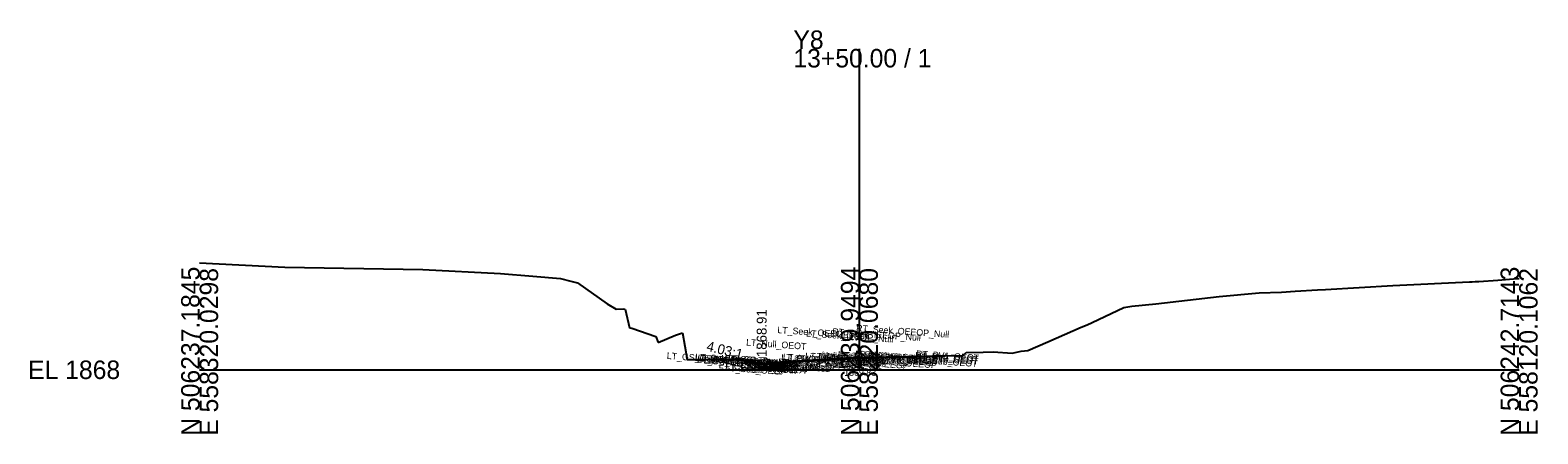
# Model space of a CAD drawing. Extents: x -26 to 203, y -10 to 8070.
# Drawn here: x -25.7 to 202.8, y 3490.3 to 3551.4 of the extents above; entities that cross this region are included whole.
import ezdxf

# ---------------------------------------------------------------- set-up
doc = ezdxf.new("R2010")
doc.units = 0
for name, color, linetype in [('Default', 7, 'Continuous'), ('Exist Cross Section Cell', 7, 'Continuous'), ('Exist XS Center Line Elevation Label', 7, 'Continuous'), ('Exist XS Ground Line', 7, 'Continuous'), ('Prop CMT Conc Surface', 7, 'Continuous'), ('Prop CMT Concrete Structures', 7, 'Continuous'), ('Prop CMT Pvmt Course 1', 7, 'Continuous'), ('Prop CMT Pvmt Course 1 CG', 7, 'Continuous'), ('Prop CMT Pvmt Course 2', 7, 'Continuous'), ('Prop CMT Pvmt Course 3', 7, 'Continuous'), ('Prop CMT Pvmt Surface', 7, 'Continuous'), ('Prop CMT Slope Grass', 7, 'Continuous'), ('Prop CMT Subgrade Earthwork', 7, 'Continuous'), ('Prop XS Earthwork Shape', 7, 'Continuous'), ('Prop XS Hydro Elevations', 7, 'Continuous'), ('Prop XS Side Slope Text', 7, 'Continuous'), ('Typical Text Grade Point CELL', 7, 'Continuous')]:
    doc.layers.add(name, color=color, linetype=linetype)

msp = doc.modelspace()

# ---------------------------------------------------------------- linework, layer by layer
at = {"layer": 'Exist Cross Section Cell'}
for p, q in [((100, 3500), (100, 3548.56)), ((0, 3500), (100, 3500)), ((100, 3500), (200, 3500))]:
    msp.add_line(p, q, dxfattribs=at)
at = {"layer": 'Exist XS Ground Line'}
for p, q in [((0, 3516.19), (12.91, 3515.51)), ((12.91, 3515.51), (33.83, 3515.19)), ((33.83, 3515.19), (45.59, 3514.57)), ((45.59, 3514.57), (50.52, 3514.17)), ((50.52, 3514.17), (54.72, 3513.79)), ((54.72, 3513.79), (56.24, 3513.4)), ((56.24, 3513.4), (57.29, 3513.14)), ((57.29, 3513.14), (61.75, 3510)), ((170.64, 3512.16), (180.87, 3512.74)), ((180.87, 3512.74), (192.5, 3513.31)), ((192.5, 3513.31), (192.88, 3513.33)), ((192.88, 3513.33), (193.33, 3513.34)), ((193.33, 3513.34), (193.91, 3513.35)), ((193.91, 3513.35), (196.79, 3513.55)), ((196.79, 3513.55), (199.13, 3513.74)), ((199.13, 3513.74), (200, 3513.8)), ((144.93, 3509.99), (154.51, 3511.07)), ((154.51, 3511.07), (160.62, 3511.63)), ((160.62, 3511.63), (163.97, 3511.76)), ((163.97, 3511.76), (166.08, 3511.88)), ((166.08, 3511.88), (169.43, 3512.09)), ((169.43, 3512.09), (170.64, 3512.16)), ((61.75, 3510), (63.11, 3509.15)), ((63.11, 3509.15), (64.18, 3509.2)), ((64.18, 3509.2), (64.5, 3509.19)), ((64.5, 3509.19), (65.15, 3506.35)), ((135.29, 3507.16), (140.06, 3509.41)), ((140.06, 3509.41), (141.29, 3509.61)), ((141.29, 3509.61), (144.93, 3509.99)), ((65.15, 3506.35), (65.51, 3506.32)), ((65.51, 3506.32), (69.16, 3505.02)), ((128.55, 3504.23), (133.62, 3506.43)), ((133.62, 3506.43), (134.53, 3506.82)), ((134.53, 3506.82), (135.29, 3507.16)), ((69.16, 3505.02), (69.49, 3504.12)), ((69.49, 3504.12), (72.11, 3505.22)), ((72.11, 3505.22), (73.2, 3505.61)), ((73.2, 3505.61), (73.89, 3501.56)), ((125.55, 3502.93), (128.55, 3504.23)), ((73.89, 3501.56), (74.57, 3501.54)), ((74.57, 3501.54), (75.66, 3501.54)), ((75.66, 3501.54), (78.42, 3501.56)), ((78.42, 3501.56), (80.12, 3501.53)), ((80.12, 3501.53), (83.51, 3501.43)), ((83.51, 3501.43), (84.06, 3500.96)), ((85.69, 3501.01), (88.95, 3501.21)), ((88.95, 3501.21), (99.03, 3501.81)), ((99.03, 3501.81), (100, 3501.83)), ((100, 3501.83), (100.64, 3501.84)), ((100.64, 3501.84), (113.89, 3502.17)), ((113.89, 3502.17), (114.62, 3502.17)), ((114.62, 3502.17), (115.63, 3502.11)), ((115.63, 3502.11), (116.21, 3502.61)), ((116.21, 3502.61), (118.75, 3502.68)), ((118.75, 3502.68), (120.28, 3502.73)), ((120.28, 3502.73), (123.18, 3502.51)), ((123.18, 3502.51), (124.52, 3502.8)), ((124.52, 3502.8), (125.55, 3502.93)), ((84.06, 3500.96), (84.5, 3500.97)), ((84.5, 3500.97), (85.69, 3501.01))]:
    msp.add_line(p, q, dxfattribs=at)
at = {"layer": 'Prop CMT Conc Surface'}
for points in [[(85.19, 3500.91), (85.19, 3501.41), (84.69, 3501.41)], [(87.19, 3501.1), (85.19, 3500.91)]]:
    msp.add_lwpolyline(points, dxfattribs=at)
at = {"layer": 'Prop CMT Concrete Structures'}
for points in [[(87.19, 3501.1), (85.19, 3500.91), (85.19, 3501.41), (84.69, 3501.41)], [(84.69, 3501.41), (84.69, 3500.38), (87.19, 3500.52)], [(87.19, 3500.52), (87.19, 3501.1)]]:
    msp.add_lwpolyline(points, dxfattribs=at)
at = {"layer": 'Prop CMT Pvmt Course 1'}
for points in [[(99.98, 3501.83), (97.98, 3501.75), (97.97, 3501.75), (93.99, 3501.51), (93.98, 3501.51), (87.19, 3501.1)], [(99.98, 3501.83), (101.98, 3501.88), (101.99, 3501.88), (105.97, 3501.98), (105.98, 3501.98), (112.77, 3502.14)], [(87.19, 3501.1), (87.19, 3500.85)], [(87.19, 3500.85), (88.69, 3500.94)]]:
    msp.add_lwpolyline(points, dxfattribs=at)
at = {"layer": 'Prop CMT Pvmt Course 1 CG'}
for points in [[(87.19, 3500.52), (84.19, 3500.35), (83.88, 3500.04)], [(83.88, 3500.04), (87.19, 3500.23)], [(87.19, 3500.23), (87.19, 3500.52)]]:
    msp.add_lwpolyline(points, dxfattribs=at)
at = {"layer": 'Prop CMT Pvmt Course 2'}
for points in [[(88.69, 3500.94), (87.19, 3500.85)], [(87.19, 3500.85), (87.19, 3500.6)], [(87.19, 3500.6), (88.69, 3500.69)]]:
    msp.add_lwpolyline(points, dxfattribs=at)
at = {"layer": 'Prop CMT Pvmt Course 3'}
for points in [[(88.69, 3500.69), (87.19, 3500.6)], [(87.19, 3500.6), (87.19, 3500.23)], [(87.19, 3500.23), (88.69, 3500.31)]]:
    msp.add_lwpolyline(points, dxfattribs=at)
at = {"layer": 'Prop CMT Pvmt Surface'}
for points in [[(99.98, 3501.83), (97.98, 3501.75), (97.97, 3501.75), (93.99, 3501.51), (93.98, 3501.51), (87.19, 3501.1)], [(99.98, 3501.83), (101.98, 3501.88), (101.99, 3501.88), (105.97, 3501.98), (105.98, 3501.98), (112.77, 3502.14)]]:
    msp.add_lwpolyline(points, dxfattribs=at)
at = {"layer": 'Prop CMT Slope Grass'}
msp.add_lwpolyline([(84.69, 3501.41), (79.19, 3501.52), (79.07, 3501.55)], dxfattribs=at)
at = {"layer": 'Prop CMT Subgrade Earthwork'}
for points in [[(87.19, 3500.23), (83.88, 3500.04), (82.47, 3501.45)], [(88.69, 3500.31), (88.69, 3501.19)], [(88.69, 3500.31), (87.19, 3500.23)]]:
    msp.add_lwpolyline(points, dxfattribs=at)
at = {"layer": 'Prop XS Earthwork Shape'}
for points in [[(82.47, 3501.45), (79.19, 3501.52), (79.07, 3501.55), (80.12, 3501.53)], [(82.47, 3501.45), (83.51, 3501.43), (84.06, 3500.96), (84.5, 3500.97), (85.19, 3500.91), (87.19, 3501.1), (88.95, 3501.21), (93.99, 3501.51), (97.98, 3501.75), (99.98, 3501.83), (100.64, 3501.84), (101.98, 3501.88), (105.97, 3501.98), (112.77, 3502.14), (112.77, 3502.02), (100, 3501.7), (88.69, 3501.06), (88.69, 3500.31), (87.19, 3500.23), (83.88, 3500.04)], [(97.98, 3501.75), (99.03, 3501.81), (99.98, 3501.83)], [(85.69, 3501.01), (87.19, 3501.1), (85.19, 3500.91)]]:
    msp.add_lwpolyline(points, close=True, dxfattribs=at)

# ---------------------------------------------------------------- texts
at = {"layer": 'Default'}
msp.add_text('-', height=0.0001, dxfattribs=at).set_placement((0, 3500))
at = {"layer": 'Exist Cross Section Cell'}
for s, p in [('Y8', (90, 3548.56)), ('13+50.00 / 1', (90, 3545.76)), ('EL 1868', (-26, 3498.6))]:
    msp.add_text(s, height=2.8, dxfattribs=at).set_placement(p)
for s, p in [('N 506237.1845', (0, 3490)), ('E 558320.0298', (2.8, 3490)), ('N 506239.9494', (100, 3490)), ('E 558220.0680', (102.8, 3490)), ('N 506242.7143', (200, 3490)), ('E 558120.1062', (202.8, 3490))]:
    msp.add_text(s, height=2.8, rotation=90, dxfattribs=at).set_placement(p)
at = {"layer": 'Exist XS Center Line Elevation Label'}
msp.add_text('1869.83', height=1, dxfattribs=at).set_placement((97.7, 3499.08))
at = {"layer": 'Prop XS Hydro Elevations'}
msp.add_text('1868.91', height=1.5, rotation=90, dxfattribs=at).set_placement((85.94, 3501.91))
at = {"layer": 'Prop XS Side Slope Text'}
msp.add_text('4.03:1', height=1.5, rotation=346.0614, dxfattribs=at).set_placement((76.72, 3502.91))
at = {"layer": 'Typical Text Grade Point CELL'}
for s, p in [('LT_Seek_OEEOP_Null', (87.54, 3505.56)), ('LT_Seek_IEEOP_Null', (91.91, 3505.04)), ('RT_Seek_IEEOP_Null', (95.86, 3505.29)), ('RT_Seek_OEEOP_Null', (99.48, 3505.82)), ('LT_Null_OEOT', (82.81, 3503.67)), ('LT_GS_OS_GR_Face_Graphics', (70.78, 3501.64)), ('LT_Slope_Cut', (75.04, 3501.33)), ('LT_Sub_Trench_Out_DLT', (75.1, 3501.47)), ('LT_GS_OS_GR_Face_Graphics1', (75.37, 3501.05)), ('LT_CSLP_Pnt', (75.47, 3501.28)), ('LT_CG_MatchPVSlope_Null', (77.12, 3501.05)), ('LT_CG1_Shelf_Out', (78.66, 3500.23)), ('LT_CG_Top_BOC', (79.58, 3501.27)), ('LT_CG_Bot_BOC', (79.71, 3500.22)), ('LT_CG_Top_Face', (80.09, 3501.26)), ('LT_CG_Top_Gut', (80.36, 3500.75)), ('LT_PV2_OEOT', (82.91, 3500.65)), ('LT_PV3_OEOT', (82.91, 3500.4)), ('LT_PV1_OEOT', (83.03, 3500.89)), ('LT_CG_Bot_IE', (83.09, 3500.3)), ('LT_PV_Sub_Tie_Out', (88.13, 3501.42)), ('LT_Null OEEOP Test', (88.38, 3501.46)), ('LT_PV2_OEEOP', (89.35, 3501.06)), ('LT_PV3_OEEOP', (89.35, 3500.81)), ('LT_Sub_OEEOP', (89.38, 3500.43)), ('LT_PV1_OEEOP', (89.47, 3501.18)), ('LT_Pvmt Out', (90.23, 3501.27)), ('LT_Null IEEOP Test', (91.76, 3501.62)), ('LT_PV_Sub_Tie_In', (92.74, 3501.61)), ('LT_PV2_IEEOP', (93.73, 3501.26)), ('LT_PV3_IEEOP', (93.73, 3501.01)), ('LT_Sub_IEEOP', (93.75, 3500.64)), ('LT_PV1_IEEOP', (93.85, 3501.38)), ('Null RT Pvmt Slope', (94.24, 3501.73)), ('Null LT Pvmt Slope', (94.3, 3501.76)), ('PV1_Overlay_Null', (94.73, 3501.57)), ('LT_Pvmt In', (94.82, 3501.47)), ('RT_PV_Sub_Tie_In', (96.68, 3501.75)), ('RT_Null IEEOP Test', (96.7, 3501.79)), ('Sub_PGL', (97.33, 3500.64)), ('PV2_PGL', (97.3, 3501.27)), ('PV3_PGL', (97.3, 3501.02)), ('PV1_PGL', (97.42, 3501.51)), ('RT_PV2_IEEOP', (97.67, 3501.43)), ('RT_PV3_IEEOP', (97.67, 3501.18)), ('RT_Sub_IEEOP', (97.7, 3500.8)), ('RT_PV1_IEEOP', (97.79, 3501.55)), ('RT_Pvmt In', (98.78, 3501.6)), ('CL', (99.18, 3501.42)), ('RT_Null OEEOP Test', (99.32, 3501.89)), ('RT_PV_Sub_Tie_Out', (100.07, 3501.89)), ('RT_PV2_OEEOP', (101.29, 3501.55)), ('RT_PV3_OEEOP', (101.29, 3501.3)), ('RT_Sub_OEEOP', (101.32, 3500.93)), ('RT_PV1_OEEOP', (101.41, 3501.67)), ('RT_Pvmt Out', (102.15, 3501.74)), ('RT_PV2_OEOT', (108.43, 3501.69)), ('RT_PV3_OEOT', (108.43, 3501.44)), ('RT_Sub_OEOT', (108.46, 3501.07)), ('RT_PV1_OEOT', (108.55, 3501.94)), ('LT_Sub_OEOP', (79.62, 3499.84)), ('LT_Sub_OEOT', (82.94, 3500.02))]:
    msp.add_text(s, height=1, rotation=356, dxfattribs=at).set_placement(p)

doc.saveas('drawing.dxf')
